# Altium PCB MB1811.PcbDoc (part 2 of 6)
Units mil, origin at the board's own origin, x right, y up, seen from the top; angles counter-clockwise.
Board outline 3480.3 x 4291.34 mil, 4 copper layers (Top Layer, L2_VCC, L3_GND, Bottom Layer), stack 30.59 mil thick; 371 components, 285 nets, 1369 pads, 606 vias.
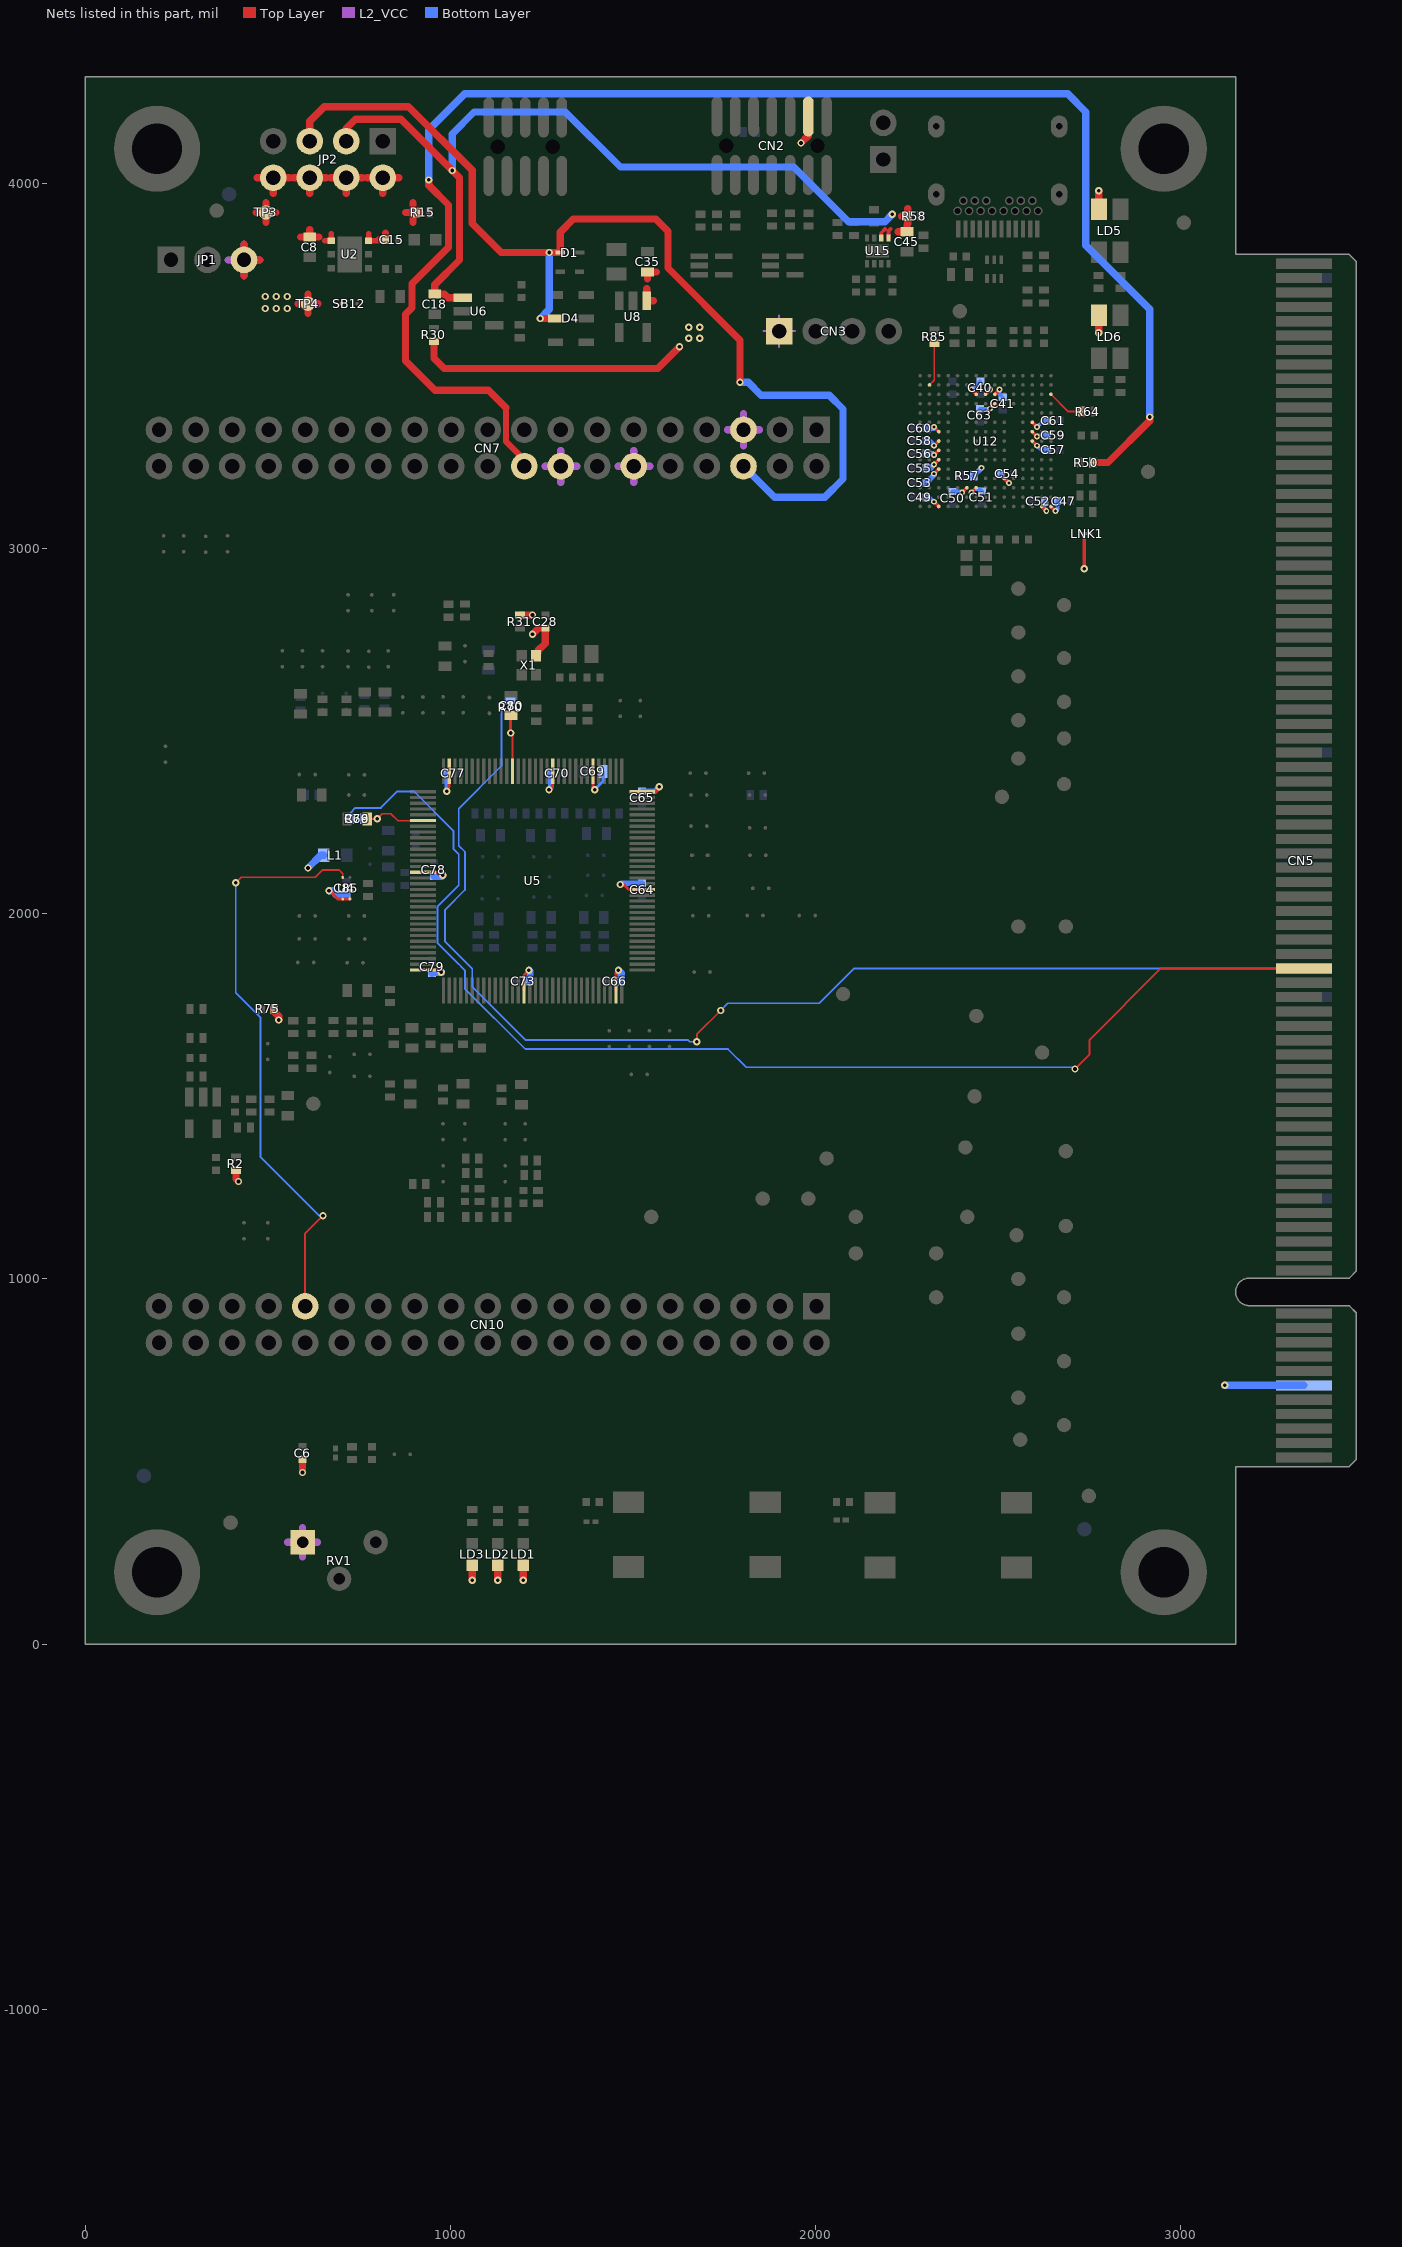
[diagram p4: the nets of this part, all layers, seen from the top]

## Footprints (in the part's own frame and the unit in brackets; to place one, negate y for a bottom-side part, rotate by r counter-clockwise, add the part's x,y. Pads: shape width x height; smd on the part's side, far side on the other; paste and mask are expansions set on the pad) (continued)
ICC_UFBGA201_176+25_10X10_P065 [mm] "IPC"
  round 0.25 smd mask+0.05: A1(-4.55,4.55) A2(-3.9,4.55) A3(-3.25,4.55) A4(-2.6,4.55) A5(-1.95,4.55) A6(-1.3,4.55) A7(-0.65,4.55) A8(0,4.55) A9(0.65,4.55) A10(1.3,4.55) A11(1.95,4.55) A12(2.6,4.55) A13(3.25,4.55) A14(3.9,4.55) A15(4.55,4.55) B1(-4.55,3.9) B2(-3.9,3.9) B3(-3.25,3.9) B4(-2.6,3.9) B5(-1.95,3.9) B6(-1.3,3.9) B7(-0.65,3.9) B8(0,3.9) B9(0.65,3.9) B10(1.3,3.9) B11(1.95,3.9) B12(2.6,3.9) B13(3.25,3.9) B14(3.9,3.9) B15(4.55,3.9) C1(-4.55,3.25) C2(-3.9,3.25) C3(-3.25,3.25) C4(-2.6,3.25) C5(-1.95,3.25) C6(-1.3,3.25) C7(-0.65,3.25) C8(0,3.25) C9(0.65,3.25) C10(1.3,3.25) C11(1.95,3.25) C12(2.6,3.25) C13(3.25,3.25) C14(3.9,3.25) C15(4.55,3.25) D1(-4.55,2.6) D2(-3.9,2.6) D3(-3.25,2.6) D4(-2.6,2.6) D5(-1.95,2.6) D6(-1.3,2.6) D7(-0.65,2.6) D8(0,2.6) D9(0.65,2.6) D10(1.3,2.6) D11(1.95,2.6) D12(2.6,2.6) D13(3.25,2.6) D14(3.9,2.6) D15(4.55,2.6) E1(-4.55,1.95) E2(-3.9,1.95) E3(-3.25,1.95) E4(-2.6,1.95) E12(2.6,1.95) E13(3.25,1.95) E14(3.9,1.95) E15(4.55,1.95) F1(-4.55,1.3) F2(-3.9,1.3) F3(-3.25,1.3) F4(-2.6,1.3) F6(-1.3,1.3) F7(-0.65,1.3) F8(0,1.3) F9(0.65,1.3) F10(1.3,1.3) F12(2.6,1.3) F13(3.25,1.3) F14(3.9,1.3) F15(4.55,1.3) G1(-4.55,0.65) G2(-3.9,0.65) G3(-3.25,0.65) G4(-2.6,0.65) G6(-1.3,0.65) G7(-0.65,0.65) G8(0,0.65) G9(0.65,0.65) G10(1.3,0.65) G12(2.6,0.65) G13(3.25,0.65) G14(3.9,0.65) G15(4.55,0.65) H1(-4.55,0) H2(-3.9,0) H3(-3.25,0) H4(-2.6,0) H6(-1.3,0) H7(-0.65,0) H8(0,0) H9(0.65,0) H10(1.3,0) H12(2.6,0) H13(3.25,0) H14(3.9,0) H15(4.55,0) J1(-4.55,-0.65) J2(-3.9,-0.65) J3(-3.25,-0.65) J4(-2.6,-0.65) J6(-1.3,-0.65) J7(-0.65,-0.65) J8(0,-0.65) J9(0.65,-0.65) J10(1.3,-0.65) J12(2.6,-0.65) J13(3.25,-0.65) J14(3.9,-0.65) J15(4.55,-0.65) K1(-4.55,-1.3) K2(-3.9,-1.3) K3(-3.25,-1.3) K4(-2.6,-1.3) K6(-1.3,-1.3) K7(-0.65,-1.3) K8(0,-1.3) K9(0.65,-1.3) K10(1.3,-1.3) K12(2.6,-1.3) K13(3.25,-1.3) K14(3.9,-1.3) K15(4.55,-1.3) L1(-4.55,-1.95) L2(-3.9,-1.95) L3(-3.25,-1.95) L4(-2.6,-1.95) L12(2.6,-1.95) L13(3.25,-1.95) L14(3.9,-1.95) L15(4.55,-1.95) M1(-4.55,-2.6) M2(-3.9,-2.6) M3(-3.25,-2.6) M4(-2.6,-2.6) M5(-1.95,-2.6) M6(-1.3,-2.6) M7(-0.65,-2.6) M8(0,-2.6) M9(0.65,-2.6) M10(1.3,-2.6) M11(1.95,-2.6) M12(2.6,-2.6) M13(3.25,-2.6) M14(3.9,-2.6) M15(4.55,-2.6) N1(-4.55,-3.25) N2(-3.9,-3.25) N3(-3.25,-3.25) N4(-2.6,-3.25) N5(-1.95,-3.25) N6(-1.3,-3.25) N7(-0.65,-3.25) N8(0,-3.25) N9(0.65,-3.25) N10(1.3,-3.25) N11(1.95,-3.25) N12(2.6,-3.25) N13(3.25,-3.25) N14(3.9,-3.25) N15(4.55,-3.25) P1(-4.55,-3.9) P2(-3.9,-3.9) P3(-3.25,-3.9) P4(-2.6,-3.9) P5(-1.95,-3.9) P6(-1.3,-3.9) P7(-0.65,-3.9) P8(0,-3.9) P9(0.65,-3.9) P10(1.3,-3.9) P11(1.95,-3.9) P12(2.6,-3.9) P13(3.25,-3.9) P14(3.9,-3.9) P15(4.55,-3.9) R1(-4.55,-4.55) R2(-3.9,-4.55) R3(-3.25,-4.55) R4(-2.6,-4.55) R5(-1.95,-4.55) R6(-1.3,-4.55) R7(-0.65,-4.55) R8(0,-4.55) R9(0.65,-4.55) R10(1.3,-4.55) R11(1.95,-4.55) R12(2.6,-4.55) R13(3.25,-4.55) R14(3.9,-4.55) R15(4.55,-4.55)
  silkscreen extent -5.22,-5.07 5.07,5.23, body extent -5.07,-5.07 5.07,5.07, height 0.61
ICC_WSON8-EPAD_2X2_P050 [mm] "MCD-02194"
  rect 0.5x0.3 smd paste+0 mask+0.05: 1(-0.9,0.75) 2(-0.9,0.25) 3(-0.9,-0.25) 4(-0.9,-0.75) 5(0.9,-0.75) 6(0.9,-0.25) 7(0.9,0.25) 8(0.9,0.75)
  rect 0.9x1.6 smd paste+0 mask+0.05: 9(0,0)
  silkscreen extent -0.5,-1 0.5,1, body extent -1,-1 1,1, height 0.81
L0603 [mm]
  rect 0.8x0.95 smd mask+0.05: 1(-0.8,0) 2(0.8,0)
  silkscreen extent -1.33,-0.6 1.33,0.6, body extent -0.87,-0.47 0.87,0.47, height 0.95
LED_0603_OSRAM_LG-Q396-PS-35_GREEN_1A2K_H0P4 [mm]
  rect 0.8x0.8 smd mask+0.05: 1(-0.75,0) 2(0.75,0)
  silkscreen extent -0.85,-0.53 1.28,0.53, body extent -0.85,-0.45 0.85,0.45, height 0.6
LED_0603_OSRAM_LY-Q396-P1Q2-36_YELLOW_1A2K_H0P4 [mm]
  rect 0.8x0.8 smd mask+0.05: 1(-0.75,0) 2(0.75,0)
  silkscreen extent -0.85,-0.53 1.28,0.53, body extent -0.85,-0.45 0.85,0.45, height 0.4
LED_0603_VISHAY_VLMS1300-GS08_RED_1A2K_H0P8 [mm]
  rect 0.8x0.8 smd mask+0.05: 1(-0.75,0) 2(0.75,0)
  silkscreen extent -0.85,-0.53 1.28,0.53, body extent -0.85,-0.45 0.85,0.45, height 0.8
LED_BI-GR_WE-150141SV73110 [mm] "MCD-02631"
  rect 1.1x1.5 smd mask+0.05: 1(-0.75,1.5) 2(0.75,1.5) 3(-0.75,-1.5) 4(0.75,-1.5)
  silkscreen extent -1.65,-1.85 1.5,1.7, body extent -1.5,-1.85 1.5,1.85, height 2.1
LINK200 [mm]
  rect 0.2x0.35 smd paste-10 mask+0.05: 1(0,-0.225) 2(0,0.225)
MOS_SOT23-5L [mm]
  rect 0.6x1.3 smd mask+0.05: 1(-0.95,-1.1) 2(0,-1.1) 3(0.95,-1.1) 4(0.95,1.1) 5(-0.95,1.1)
  silkscreen extent -1.6,-0.95 1.6,0.97, body extent -1.52,-1.25 1.52,1.25, height 1.45
POT_BOURNS_3386P-1-101TLF [mm] "MCD-02026"
  rect 1.7x1.7 hole 0.8 mask+0.05: 1(-2.54,0.02)
  round 1.7 hole 0.8 mask+0.05: 2(0,-2.52) 3(2.54,0.02)
  silkscreen extent -4.8,-4.8 4.8,4.8, body extent -4.8,-4.8 4.8,5.04, height 10.42
PTH_M1261-3005-N_3P5X6_M3_H14 [mm]
  round 6 hole 3.5 mask+0.05: 1(0,0)
  silkscreen extent -3.25,-3.25 3.25,3.25, body extent -2.5,-2.5 2.5,2.5, height 14
R0402 [mm]
  rect 0.51x0.7 smd mask+0.05: 1(-0.45,0) 2(0.45,0)
  body extent -0.52,-0.3 0.52,0.3, height 0.4
SOLDER-BRIDGE_R0603-0R [mil]
  round 10 smd paste-393.7: 1(-19.68,0) 2(23.62,0)
  Top Layer region: -47.24,-19.68 -47.24,19.68 -15.75,19.68 3.94,0 -15.75,-19.68 -47.24,-19.68
  Top Layer region: -5.91,19.68 13.78,0 -5.91,-19.68 47.24,-19.68 47.24,19.68 -5.91,19.68
  silkscreen extent -50,-23 50,23, body extent -36,-20 36,20, height 22
STICKER_BOARD_25X9 [mil] "Sticker to mention board CPN code"
  silkscreen extent -492,-177 492,177
STICKER_PRODUCT_25X9 [mil] "Sticker to mention board CPN code"
  silkscreen extent -492,-177 492,177
SWI_WEALTHMETAL_TD-0341_4P_BLACK [mm]
  rect 1.52x2.16 smd mask+0.05: 1(-2.25,-4.75) 2(-2.25,4.75) 3(2.25,-4.75) 4(2.25,4.75)
  silkscreen extent -3,-3.5 3,3.5, body extent -3,-5.15 3,5.15, height 7.55
SWI_WEALTHMETAL_TD-0341_4P_BLUE [mm]
  rect 1.52x2.16 smd mask+0.05: 1(-2.25,-4.75) 2(-2.25,4.75) 3(2.25,-4.75) 4(2.25,4.75)
  silkscreen extent -3,-3.5 3,3.5, body extent -3,-5.15 3,5.15, height 7.55
TP_SMD_1MM [mm]
  round 1 smd paste-10 mask+0.05: 1(0,0)
  silkscreen extent -0.7,-0.7 0.7,0.7

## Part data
B1: library part MCD-00001, "Push Button, NC, 0.1A, 24V, Black", Manufacturer=WEALTHMETAL, Manufacturer_Part_Number=TD-0341X-A00, Package=6x6mm
B2: library part MCD-00002, "Push Button, NC, 0.1A, 24V, Blue", Manufacturer=WEALTHMETAL, Manufacturer_Part_Number=TD-0341X-GO0, Package=6x6mm
C1 C7 C22 C26: library part MCD-00198, "Capacitor, MLCC, 1nF, 16V, X7R, +/-10%, 0402, T=0.5mm", Manufacturer=YAGEO, Manufacturer_Part_Number=CC0402KRX7R7BB102, Package=0402
C2 C6 C11 C14 C15 C28 C30 C37 C64 C65 C66 C70 C73 C77 C78 C79 C81 C85 C86: library part MCD-00102, "Capacitor, MLCC, 100nF, 16V, X7R, +/-10%, 0402, T=0.5mm", Manufacturer=YAGEO, Manufacturer_Part_Number=CC0402KRX7R7BB104, Package=0402
C3: library part MCD-00012, "Capacitor, MLCC, 2.2uF, 10V, X5R, +/- 10%, 0603, T=0.8mm", Manufacturer=YAGEO, Manufacturer_Part_Number=CC0603KRX5R6BB225, Package=0603
C4 C5 C9 C10 C13 C16 C17 C19 C20 C21 C23 C24 C25 C67 C68 C71 C72 C74 C75 C76 C80: library part MCD-02457, "Capacitor, MLCC, 2.2nF, 50V, C0G/NPO, +/-5%, 0603, T=0,8mm", Manufacturer=YAGEO, Manufacturer_Part_Number=CC0603JRNPO9BN222, Package=0603
C8 C12 C83 C84: library part MCD-00010, "Capacitor, MLCC, 1uF, 16V, X5R, +/-10%, 0603, T=0.8mm", Manufacturer=YAGEO, Manufacturer_Part_Number=CC0603KRX5R7BB105, Package=0603
C18 C35 C45: library part MCD-00099, "Capacitor, MLCC, 10uF, 10V, X5R, +/-10%, 0603, T=0.8mm", Manufacturer=MURATA, Manufacturer_Part_Number=GRM188R61A106KE69D, Package=0603
C27 C46: library part MCD-02355, "Capacitor, MLCC, 100nF, 25V, X7R, +/-10%, 0402, T=0.5mm", Manufacturer=WALSIN, Manufacturer_Part_Number=0402B104K250CT, Package=0402
C29 C31: library part MCD-01374, "Capacitor, MLCC, 5.6pF, 50V, NPO, +/-0.1pF, 0402, T=0.5mm", Manufacturer=YAGEO, Manufacturer_Part_Number=CC0402BRNPO9BN5R6, Package=0402
C32: library part MCD-02372, "Capacitor, MLCC, 2.2uF, 25V, X7R, +/-10%, 0805, T=1,25mm", Manufacturer=MURATA, Manufacturer_Part_Number=GRM21BR71E225KE11L, Package=0805
C33: library part MCD-00016, "Capacitor, MLCC, 20pF, 50V, NPO, +/- 5%, 0402, T=0.5mm", Manufacturer=YAGEO, Manufacturer_Part_Number=CC0402JRNPO9BN200, Package=0402
C34 C36 C87: library part MCD-02198, "Capacitor, MLCC, 10nF, 50V, X7R, +/-10%, 0402, T=0.5mm", Manufacturer=YAGEO, Manufacturer_Part_Number=CC0402KRX7R9BB103, Package=0402
C38 C43 C62: library part MCD-02606, "Capacitor, MLCC, 2.2uF, 6.3V, X5R, +/-10%, 0402, T=0.5mm", Manufacturer=YAGEO, Manufacturer_Part_Number=CC0402KRX5R5BB225, Package=0402
C39 C44: library part MCD-01774, "Capacitor, MLCC, 2.7pF, 50V, NPO, +/-0.1pF, 0402, T=0.5mm", Manufacturer=YAGEO, Manufacturer_Part_Number=CC0402BRNPO9BN2R7, Package=0402
C40 C41 C47 C48 C49 C50 C51 C52 C53 C54 C55 C56 C57 C58 C59 C60 C61 C63: library part MCD-00006, "Capacitor, MLCC, 100nF, 16V, X7R, +/-10%, 0402, T=0.5mm", Manufacturer=YAGEO, Manufacturer_Part_Number=CC0402KRX7R7BB104, Package=0402
C42: library part MCD-00205, "Capacitor, MLCC, 100pF, 50V, NPO, +/-5%, 0402, T=0.5mm", Manufacturer=YAGEO, Manufacturer_Part_Number=CC0402JRNPO9BN101, Package=0402
C69: library part MCD-02196, "Capacitor, MLCC, 4.7uF, 25V, X5R, +/-10%, 0603, T=0.8mm", Manufacturer=TDK, Manufacturer_Part_Number=C1608X5R1E475K080AC, Package=0603
C82: library part MCD-00011, "Capacitor, MLCC, 10nF, 16V, X7R, +/-10%, 0402, T=0.5mm", Manufacturer=YAGEO, Manufacturer_Part_Number=CC0402KRX7R7BB103, Package=0402
CN1: library part MCD-01951, "Header, 5x2, 1.27mm, VR, SMD, T=5.97mm", Manufacturer=SAMTEC, Manufacturer_Part_Number=FTSH-105-01-L-DV-K-A, Package=SMT
CN2: library part MCD-01959, "Header, 7x2, 1.27mm, VR, SMD, T=5.97mm", Manufacturer=SAMTEC, Manufacturer_Part_Number=FTSH-107-01-L-DV-K-A, Package=SMT
CN3: library part MCD-00029, "Header, 4x1, 2.54mm, VR, TH, T=5.84mm/2.54mm", Manufacturer=SAMTEC, Manufacturer_Part_Number=TSW-104-07-G-S
CN4: library part MCD-01108, "USB_TypeC, SMD+DIP, T= 2.96mm (for 1.6mm pcb)", Alternate_Manufacturer=Wurth, Alternate_Manufacturer_Part_Number=632723300011, Manufacturer="CHANT SINCERE (COXOC)", Manufacturer_Part_Number=317JD24BZTF3K3C3
CN5: library part MCD-02436, "PCI EXPRESS x16 Add-in Card Edge-Finger", Manufacturer=N/A
CN7 CN10: library part MCD-00213, "Header, 19x2, 2.54mm, VR, TH, T=5.84mm/10.16mm", Manufacturer=SAMTEC, Manufacturer_Part_Number=TSW-119-09-G-D
D1 D2: library part MCD-01677, "Small signal Schottky diodes", Manufacturer=STMICROELECTRONICS, Manufacturer_HQ_COO=EU, Manufacturer_Part_Number=BAT54KFILM, Package=SOD-523
D3 D4 D5: library part MCD-03011, "Signal Schottky Diode, If=1A, Ifsm=5A, Vf =0.54V@1A, Vrrm=23V, Ir = 0.65µA@5V, SOD-323", Manufacturer=STMICROELECTRONICS, Manufacturer_Part_Number=BAT20JFILM, Package=SOD-323
H1 H2 H3 H4: library part MCD-00035, "POSITION HOLE C6D3R5", Manufacturer=N/A, Manufacturer_Part_Number=n/a
HW1: library part MCD-00235, "Sticker Board 25x9 mm", Manufacturer=N/A
HW2: library part MCD-00547, "Sticker product 25x9 mm", Manufacturer=N/A
JP1: library part MCD-01905, "Header, 3x1, 2.54mm, VR, TH, T=5.84mm/2.54mm", Manufacturer=SAMTEC, Manufacturer_Part_Number=TSW-103-07-G-S
JP2: library part MCD-00686, "Header, 4x2, 2.54mm, VR, TH, T=5.84mm/2.54mm", Manufacturer=SAMTEC, Manufacturer_Part_Number=TSW-104-07-G-D
JP3: library part MCD-00045, "Header, 2x1, 2.54mm, VR, TH, T=5.84mm/2.54mm", Manufacturer=SAMTEC, Manufacturer_Part_Number=TSW-102-07-G-S
L1: library part MCD-00047, "Ferrite bead, 600R @1 00MHz, +/-25%, 350mA, 0R5, 0603, T=0.8mm", Manufacturer=TAI-TECH, Manufacturer_Part_Number=FCM1608KF-601T03, Package=0603
LD1 LD4: library part MCD-00588, "LED Green, 0603 SMD, Forward Voltage Typ=2V, Max=2.5V", Manufacturer="OSRAM OPTO SEMICONDUCTORS", Manufacturer_Part_Number="LG Q396-PS-35", Package="LED 0603"
LD2: library part MCD-00587, "LED Red, 0603 SMD, 2V Forward Voltage", Manufacturer=VISHAY, Manufacturer_Part_Number=VLMS1300-GS08, Package="LED 0603"
LD3: library part MCD-01061, "LED Yellow, 0603 SMD, Forward Voltage min=1.7V, Typ=2V, Max=2.3V", Manufacturer="OSRAM OPTO SEMICONDUCTORS", Manufacturer_Part_Number="LY Q396-P1Q2-36"
LD5 LD6: library part MCD-02631, "LED Bicolor, Green/Red, 2V, 20mA,  4-PLCC", Manufacturer="WURTH ELEKTRONIK", Manufacturer_Part_Number=150141SV73110, Package=4-PLCC
LNK1: library part MCD-02777, "Track link on PCB 200um width for layout routing.", Manufacturer=N/A
R1 R36 R49 R90: library part MCD-00067, "Resistor, 100R, 0402, +/- 1%, 1/16W", Manufacturer=YAGEO, Manufacturer_Part_Number=RC0402FR-07100RL, Package=0402
R2: library part MCD-02456, "Resistor, 4R7, 0402, +/-5%, 1/16W, +/-200ppm/°C", Manufacturer=YAGEO, Manufacturer_Part_Number=RC0402JR-074R7L, Package=0402
R3 R4 R12 R31 R51 R52 R53 R57 R60 R77: library part MCD-00053, "Resistor, 10K, 0402, +/-1%, 1/16W", Manufacturer=YAGEO, Manufacturer_Part_Number=RC0402FR-0710KL, Package=0402
R5 R11 R17 R22 R26 R33 R78 R79 R80 R81 R82 R83: library part MCD-02979, "Resistor, 30K, 0402, +/-0.1%, 1/16W, +/-25ppm/°C", Manufacturer=YAGEO, Manufacturer_Part_Number=RT0402BRD0730KL, Package=0402
R6 R7 R18 R24 R27 R37: library part MCD-02418, "Resistor, 1K, 0402, +/-0.1%, 1/16W, +/-50ppm/°C", Manufacturer=YAGEO, Manufacturer_Part_Number=RT0402BRE071KL, Package=0402
R8 R10 R13 R14 R16 R19 R20 R21 R25 R29 R61 R62 R65 R66 R67 R68 R69 R70 R71 R72 R73: library part MCD-00427, "Resistor, 220R, 0402, +/-1%, 1/16W", Manufacturer=YAGEO, Manufacturer_Part_Number=RC0402FR-07220RL, Package=0402
R9: library part MCD-00481, "Resistor, 47R, 0402, +/-1%, 1/16W", Manufacturer=YAGEO, Manufacturer_Part_Number=RC0402FR-0747RL, Package=0402
R15 R63: library part MCD-00409, "Resistor, 1K8, 0402, +/-1%, 1/16W", Manufacturer=YAGEO, Manufacturer_Part_Number=RC0402FR-071K8L, Package=0402
R23: library part MCD-00178, "Resistor, 470R, 0402, +/-1%, 1/16W", Manufacturer=YAGEO, Manufacturer_Part_Number=RC0402FR-07470RL, Package=0402
R28: library part MCD-00441, "Resistor, 270R, 0402, +/-1%, 1/16W", Manufacturer=YAGEO, Manufacturer_Part_Number=RC0402FR-07270RL, Package=0402
R30 R34 R54 R55 R87: library part MCD-00059, "Resistor, 100K, 0402, +/-1%, 1/16W", Manufacturer=YAGEO, Manufacturer_Part_Number=RC0402FR-07100KL, Package=0402
R32: library part MCD-00461, "Resistor, 360R, 0402, +/-1%, 1/16W", Manufacturer=YAGEO, Manufacturer_Part_Number=RC0402FR-07360RL, Package=0402
R35 R50 R56 R59: library part MCD-00333, "Resistor, 5K1, 0402, +/-1%, 1/16W", Manufacturer=YAGEO, Manufacturer_Part_Number=RC0402FR-075K1L, Package=0402
R38 R39 R41 R42 R43 R64 R74 R75 R76 R91 R92 R93 R94 R95 R96 R97 R98 R99: library part MCD-00052, "Resistor, 0R, 0402, +/-5%, 1/16W", Manufacturer=YAGEO, Manufacturer_Part_Number=RC0402JR-070RL, Package=0402
R40 R44 R45 R85: library part MCD-00455, "Resistor, 33R, 0402, +/-1%, 1/16W", Manufacturer=YAGEO, Manufacturer_Part_Number=RC0402FR-0733RL, Package=0402
R46 R89: library part MCD-00062, "Resistor, 330R, 0402, +/-1%, 1/16W", Manufacturer=YAGEO, Manufacturer_Part_Number=RC0402FR-07330RL, Package=0402
R47 R88: library part MCD-02665, "Resistor, 1K, 0402, +/-0.1%, 1/16W, +/-25ppm/°C", Manufacturer=YAGEO, Manufacturer_Part_Number=RT0402BRD071KL, Package=0402
R48 R58: library part MCD-00185, "Resistor, 3K, 0402, +/-1%, 1/16W", Manufacturer=YAGEO, Manufacturer_Part_Number=RC0402FR-073KL, Package=0402
R84: library part MCD-00381, "Resistor, 1K3, 0402, +/-1%, 1/16W", Manufacturer=YAGEO, Manufacturer_Part_Number=RC0402FR-071K3L, Package=0402
R86: library part MCD-02455, "Resistor, 3K9, 0402, +/-1%, 1/16W, +/-100ppm/°C", Manufacturer=YAGEO, Manufacturer_Part_Number=RC0402FR-073K9L, Package=0402
RV1: library part MCD-02051, "Trimmer, 10K, 3386, +/-10%, 1/2W, T=4.83mm", Manufacturer=BOURNS, Manufacturer_Part_Number=3386P-1-103TLF, Package=3386P
SB1 SB2 SB3 SB4 SB5 SB6 SB7 SB8 SB11 SB12 SB13 SB14 SB15 SB16 SB17 SB18 SB22 SB23 SB26 SB27 SB28 SB29 SB30 SB32 SB33 SB34 SB35 SB36 SB38 SB39 SB40 SB41 SB42 SB43 SB44 SB45 SB46 SB47 SB48 SB50 SB51 SB52 SB53 SB55 SB58 SB59 SB60 SB62 SB65 SB66 SB67 SB68 SB69 SB70 SB71 SB72 SB74 SB75 SB76 SB78 SB79 SB81 SB82 SB83 SB84 SB85 SB86 SB87 SB88 SB89 SB90 SB91 SB92: library part MCD-00071, "Solder Bridge ON", Manufacturer=YAGEO, Manufacturer_Part_Number=RC0603JR-070RL, Package=SB0603
SB9 SB10 SB19 SB20 SB21 SB24 SB25 SB31 SB37 SB49 SB54 SB56 SB57 SB61 SB63 SB64 SB73 SB77 SB80: library part MCD-00072, "Solder Bridge OFF", Manufacturer=YAGEO, Manufacturer_Part_Number=RC0603JR-070RL, Package=SB0603
TP1 TP2 TP3 TP4 TP5 TP6 TP7 TP8 TP9 TP10 TP11 TP12 TP13 TP14 TP15 TP16 TP17 TP18 TP19 TP20 TP21 TP22 TP23 TP24 TP25 TP26 TP27 TP28 TP29 TP30 TP31 TP32 TP33 TP34 TP35 TP36 TP37 TP38 TP39 TP40 TP41 TP42 TP43: library part MCD-00074, "Test Point 1mm", Manufacturer=N/A
U1: library part MCD-01889, "Output rail-to-rail operational amplifiers. Large output swing (+/- 2.4V at VCC  = +/- 2.5V). Operating range: 2.7V to 10V", Manufacturer=STMICROELECTRONICS, Manufacturer_HQ_COO=EU, Package=SOT23-5
U2: library part MCD-00664, "1.2 A low quiescent current LDO with reverse current protection", Manufacturer=STMICROELECTRONICS, Manufacturer_HQ_COO=EU, Package=DFN6
U3 U7 U11: library part MCD-00170, "ESD protection 6V1", Manufacturer=STMICROELECTRONICS, Manufacturer_HQ_COO=EU, Manufacturer_Part_Number=ESDALC6V1-1U2
U4: library part MCD-00668, "Low voltage 0.5 ohm single SPDT switch with break-before-make feature and 15 kV contact ESD protection", Manufacturer=STMICROELECTRONICS, Manufacturer_HQ_COO=EU, Manufacturer_Part_Number=STG4160BJR, Package="Flip Chip 8"
U5: library part MCD-02432, "MCU, Arm Cortex-M4, 32-bit MCU+FPU, up to 512 KB Flash, 128 KB SRAM", Manufacturer=STMICROELECTRONICS, Package=LQFP128
U6: library part MCD-00159, "500mA, Enhanced single channel power switches with active high enable pin", Manufacturer=STMICROELECTRONICS, Manufacturer_HQ_COO=EU
U8: library part MCD-02514, "LDO, 3.3V, 300mA, High input voltage: 2.5V to 28V, SOT23-5L", Manufacturer=STMICROELECTRONICS, Package=SOT23-5L
U9 U10: library part MCD-00136, "Dual Transil array for ESD protection", Manufacturer=STMICROELECTRONICS, Manufacturer_HQ_COO=EU
U12: library part MCD-02706, "MCU, Arm Cortex-M7 32-bit MCU, 512KB Flash, 276KB RAM, With Crypto", Manufacturer=STMICROELECTRONICS, Manufacturer_Part_Number=STM32F723IEK6, Package=BGA176
U13: library part MCD-01207, "High power Transient voltage suppressor:25V/35A EOS and ESD transients protection.", Manufacturer=STMICROELECTRONICS, Manufacturer_HQ_COO=EU, Manufacturer_Part_Number=ESDA25P35-1U1M, Package=QFN1610
U14: library part MCD-00649, "Common mode filter with ESD protection for USB 2.0 interface", Manufacturer=STMICROELECTRONICS, Manufacturer_HQ_COO=EU
U15: library part MCD-02532, "IC, eFuse with Fast Overvoltage Protection 2.7V to 18V 4A 34mOhm 8-Pin WSON", Manufacturer="TEXAS INSTRUMENTS", Package=WSON8
X1: library part MCD-01627, "Oscillator, SPXO, 24MHz, +/-50ppm, square wave, 3V3, 2x1.6mm", Manufacturer=NDK, Manufacturer_Part_Number=NZ2016SH-24MHZ-END4869F, Package=2x1.6mm
X2: library part MCD-01479, "Crystal, 32.768kHz, 6pF, +/-20ppm, 80K, 2.05x1.2mm", Manufacturer=NDK, Manufacturer_Part_Number=NX2012SA-32.768KHZ-EXS00A-MU00527, Package=2.05x1.2mm
X3: library part MCD-01036, "Crystal, 24MHz, 6pF, +/-20ppm, 80R, 2x1.6mm", Manufacturer=NDK, Manufacturer_Part_Number=NX2016SA-24MHZ-EXS00A-CS10820, Package=2x1.6mm

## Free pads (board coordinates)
  round 40 smd far side mask+40: 1(161,461) 1(394,3970) 1(2736,315)
  round 40 smd mask+40: 1(398,333) 1(2748,406) 1(3008,3892)
  round 20 on Mech16: 1(696.46,-1470.16) 1(2619.59,-1470.16)

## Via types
v1: diameter 20, hole 10, Top Layer to Bottom Layer, tented both sides, 524 vias
v2: diameter 16, hole 8, Top Layer to Bottom Layer, tented both sides, 82 vias

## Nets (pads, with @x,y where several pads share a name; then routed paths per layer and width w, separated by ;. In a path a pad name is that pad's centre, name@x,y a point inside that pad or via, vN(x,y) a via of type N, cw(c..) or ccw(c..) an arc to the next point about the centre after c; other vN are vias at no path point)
3V3: C6.2 C28.2 C64.2 C65.2 C66.2 C69.2 C70.2 C73.2 C77.2 C78.2 C79.2 C85.2 CN2.3 CN5.A06 CN7.5 CN7.12 CN7.16 JP1.3 L1.2 LD1.1 LD2.1 LD3.1 LNK1.1 R2.1 R31.2 R75.2 RV1.1 SB12.2 TP4.1 U4.4 U4.5 U5.6 U5.13 U5.31 U5.47 U5.64 U5.79 U5.95 U5.111 U5.128 X1.4 | length 2958.9
  Top Layer w8: v1(667.73,2062.75) 673.97,2056.51 675.4,2056.51 690.71,2041.2 691.55,2040.48 U4.5@724.84,2040.48 ; U5.64@924.99,1845.61 969.41,1845.59 v1(974.99,1840.01) ; U5.47@924.99,2113.32 962.39,2113.31 970.69,2105.01 v1(979.11,2105.01) ; v1(989.99,2335.01) 989.99,2342.21 996.64,2348.86 U5.31@996.64,2389.7 ; U5.79@1201.37,1789.7 1201.37,1831.39 v1(1214.99,1845.01) ; v1(1269.99,2339.69) 1270.31,2340.01 1272.11,2340.01 1280.11,2348.01 U5.13@1280.11,2389.7 ; U5.6@1390.34,2389.7 1390.34,2344.66 1394.99,2340.01 v1(1394.99,2339.65) ; U5.95@1453.34,1789.7 1453.33,1838.35 v1(1459.99,1845.01) ; v1(1464.99,2080.01) 1474.69,2080.01 1480.95,2073.75 1480.95,2073.67 1488.55,2066.06 U5.111@1524.99,2066.08 ; U5.128@1524.99,2333.79 1563.76,2333.78 1572.12,2342.14 v1(1572.12,2347.88)
  Top Layer w10: LNK1.1@2735.01,3040.7 2735.01,2945.22 v1(2735.72,2944.51)
  Top Layer w20: R2.1@412.87,1297.58 412.87,1273.7 v1(419.87,1266.7) ; 434.99,3746.56 JP1.3@434.99,3790 ; 434.99,3833.44 JP1.3@434.99,3790 ; 478.43,3790 JP1.3@434.99,3790 ; R75.2@517.59,1739.7 517.59,1731.98 529.87,1719.7 v1(529.87,1709.06) ; 583.28,3670.01 TP4.1@609.99,3670.01 ; v1(595.27,470.29) C6.2@595.27,505.6 ; 609.99,3643.3 TP4.1@609.99,3670.01 ; 609.99,3696.72 TP4.1@609.99,3670.01 ; 636.7,3670.01 TP4.1@609.99,3670.01 ; v1(1059.83,175.01) LD3.1@1059.83,216.62 ; v1(1129.83,175.01) LD2.1@1129.83,216.62 ; R31.2@1189.99,2817.72 v1(1224.87,2817.72) ; v1(1199.83,175.01) LD1.1@1199.83,216.62 ; v1(1224.99,2765.01) 1242.27,2782.29 C28.2@1259.59,2782.29 ; X1.4@1234.67,2705.59 1239.59,2712.49 1239.59,2719.61 1259.59,2739.61 C28.2@1259.59,2782.29 ; C28.2@1259.99,2782.29 C28.2@1259.59,2782.29 ; v1(1959.99,4110.01) 1979.99,4130.01 CN2.3@1979.99,4182.6
  L2_VCC w20: 391.54,3790.01 JP1.3@434.99,3790 ; 434.98,3746.57 JP1.3@434.99,3790 ; 434.98,3833.45 JP1.3@434.99,3790 ; 478.42,3790.01 JP1.3@434.99,3790 ; 554.77,279.12 RV1.1@595.27,279.11 ; 595.26,238.63 RV1.1@595.27,279.11 ; 595.26,319.61 RV1.1@595.27,279.11 ; 635.75,279.12 RV1.1@595.27,279.11 ; 1258.92,3225.01 CN7.16@1302.37,3225 ; 1302.36,3181.57 CN7.16@1302.37,3225 ; 1302.36,3268.45 CN7.16@1302.37,3225 ; 1345.8,3225.01 CN7.16@1302.37,3225 ; 1458.92,3225.01 CN7.12@1502.37,3225 ; 1502.36,3181.57 CN7.12@1502.37,3225 ; 1502.36,3268.45 CN7.12@1502.37,3225 ; 1545.8,3225.01 CN7.12@1502.37,3225 ; 1758.92,3325.01 CN7.5@1802.37,3325 ; 1802.36,3281.57 CN7.5@1802.37,3325 ; 1802.36,3368.45 CN7.5@1802.37,3325 ; 1845.8,3325.01 CN7.5@1802.37,3325
  Bottom Layer w8: v1(1394.99,2339.65) 1394.99,2340.01 1417.9,2362.92 C69.2@1417.9,2389.69
  Bottom Layer w15: v1(989.99,2335.01) 990.74,2335.76 C77.2@990.74,2384.69 ; v1(1269.99,2339.69) 1269.99,2340.01 1274.2,2344.22 C70.2@1274.2,2384.69 ; v1(1464.99,2080.01) 1468.76,2083.78 C64.2@1524.99,2083.78 ; C65.2@1524.99,2335.75 1559.99,2335.75 v1(1572.12,2347.88)
  Bottom Layer w20: v1(609.99,2125.01) 644.99,2160.01 L1.2@653.49,2160.01 ; v1(667.73,2062.75) 677.25,2062.75 687.71,2052.29 C85.2@714.99,2052.29 ; C79.2@949.99,1837.29 952.71,1840.01 v1(974.99,1840.01) ; C78.2@954.99,2102.3 976.4,2102.3 v1(979.11,2105.01) ; v1(1214.99,1845.01) 1217.7,1842.3 C73.2@1217.71,1815.01 ; v1(1459.99,1845.01) 1467.71,1837.29 C66.2@1467.71,1815.01 ; v1(3119.99,708.67) CN5.A06@3336.8,708.67
  other v1: 492.99,3657.01 522.99,3657.01 552.99,3657.01 492.99,3690.01 522.99,3690.01 552.99,3690.01
3V3_STLK: C35.2 C40.1 C41.1 C47.1 C49.1 C50.1 C51.1 C52.1 C53.1 C54.1 C55.1 C56.1 C57.1 C58.1 C59.1 C60.1 C61.1 C63.1 CN3.1 LD5.4 LD6.4 R30.1 R57.2 U8.1 U12.C1 U12.C5 U12.C6 U12.C7 U12.C8 U12.C9 U12.F3 U12.G3 U12.G13 U12.H13 U12.J12 U12.J13 U12.K4 U12.N8 U12.N9 U12.N10 U12.P1 U12.R1 | length 1972.2
  Top Layer w10: v2(2324.42,3127.78) U12.C1@2337.21,3114.98 ; v2(2324.42,3204.55) U12.C5@2337.22,3217.34 ; v2(2324.43,3230.14) U12.C6@2337.22,3242.93 ; v2(2324.42,3255.73) U12.C7@2337.21,3268.53 ; v2(2324.43,3281.32) U12.C8@2337.22,3294.12 ; v2(2324.42,3332.5) U12.C9@2337.21,3319.71 ; v2(2401.2,3153.37) U12.F3@2413.99,3166.16 ; v2(2426.79,3153.37) U12.G3@2439.58,3166.16 ; v2(2426.78,3434.86) U12.G13@2439.58,3422.07 ; U12.H13@2465.18,3422.07 v2@2477.95,3434.85 ; v2(2476.93,3382.65) U12.J12@2490.77,3396.48 ; U12.J13@2490.77,3422.07 v2(2503.55,3434.87) ; U12.K4@2516.36,3191.75 v2(2529.14,3178.97) ; U12.N8@2593.13,3294.12 v2(2605.92,3281.33) ; U12.N9@2593.13,3319.71 v2(2605.91,3306.92) ; U12.N10@2593.13,3345.3 v2(2605.91,3332.51) ; U12.P1@2618.72,3114.98 v2(2631.51,3102.19) ; U12.R1@2644.31,3114.98 v2(2657.1,3102.19)
  Top Layer w20: R30.1@954.87,3566.98 954.87,3520.8 983.07,3492.6 1567.77,3492.6 v1(1627.07,3551.9) ; 1537.27,3710.62 U8.1@1537.28,3678.01 1556.1,3678.01 ; 1539.87,3737.53 C35.2@1539.87,3757.14 1564.41,3757.15 ; v1(2775.35,3590.18) LD6.4@2775.35,3638.75 ; LD5.4@2775.35,3928.76 v1(2775.35,3979.22)
  L2_VCC w5: 1856.54,3595.01 CN3.1@1899.99,3595 ; 1899.98,3551.57 CN3.1@1899.99,3595 ; 1899.98,3638.45 CN3.1@1899.99,3595 ; 1943.42,3595.01 CN3.1@1899.99,3595
  Bottom Layer w10: C49.1@2302.6,3139.7 2312.5,3139.7 v2(2324.42,3127.78) ; C50.1@2374.7,3155.83 2375.7,3156.83 2397.74,3156.83 v2(2401.2,3153.37) ; v2(2426.79,3153.37) 2435.73,3162.31 2450.18,3162.31 C51.1@2455.18,3157.31 ; v2(2426.78,3434.86) 2444.33,3452.41 2444.87,3452.41 2449.87,3457.41 C40.1@2450.87,3457.41 ; C63.1@2449.87,3382.41 2476.69,3382.41 v2(2476.93,3382.65) ; v2(2503.55,3434.87) 2503.55,3423.03 C41.1@2512.27,3414.31 ; C54.1@2506.99,3204.12 2506.98,3201.13 v2(2529.14,3178.97) ; v2(2605.92,3281.33) 2617.67,3269.58 C57.1@2632.46,3269.58 ; v2(2605.91,3306.92) 2608.57,3309.58 C59.1@2632.46,3309.58 ; v2(2605.91,3332.51) 2622.98,3349.58 C61.1@2632.46,3349.58 ; C52.1@2627.42,3129.12 2627.42,3106.27 v2(2631.51,3102.19)
  Bottom Layer w12: v2(2657.1,3102.19) 2662.16,3107.25 C47.1@2662.16,3129.7
  Bottom Layer w15: C60.1@2302.6,3329.7 2321.62,3329.7 v2(2324.42,3332.5) ; C53.1@2302.91,3179.58 2324.42,3201.09 v2(2324.42,3204.55) ; C55.1@2302.91,3219.58 2313.87,3219.58 v2(2324.43,3230.14) ; C56.1@2302.91,3259.58 2320.57,3259.58 v2(2324.42,3255.73) ; C58.1@2302.91,3294.58 2311.17,3294.58 v2(2324.43,3281.32) ; R57.2@2432.6,3199.7 v2(2453.66,3220.77)
  other v1: 1652.57,3575.6 1682.57,3575.6 1652.57,3605.6 1682.57,3605.6
  other v2: 2477.96,3434.87
5V: C8.2 C15.2 CN7.18 JP2.2 JP2.4 JP2.6 JP2.8 R15.1 R50.2 TP3.1 U2.1 U2.6 | length 5099.7
  Top Layer w15: 656.59,3842.41 U2.1@673.81,3842.41 673.81,3861.19 ; 775.99,3861.01 776.17,3860.83 U2.6@776.18,3842.41 802.62,3842.41
  Top Layer w17: 1152.45,3385.01 1152.45,3292.56 1202.37,3242.64 CN7.18@1202.37,3225
  Top Layer w20: 468.28,3920.01 TP3.1@494.99,3920.01 ; 471.55,4015.01 JP2.8@514.99,4015.01 ; 494.99,3893.3 TP3.1@494.99,3920.01 ; 494.99,3946.72 TP3.1@494.99,3920.01 ; 514.99,3971.57 JP2.8@514.99,4015.01 ; 521.7,3920.01 TP3.1@494.99,3920.01 ; 558.43,4015.01 JP2.8@514.99,4015.01 ; 571.55,4015.01 JP2.6@614.99,4015.01 ; 590.45,3852.57 C8.2@614.99,3852.57 ; 614.99,3872.19 C8.2@614.99,3852.57 ; 614.99,3971.57 JP2.6@614.99,4015.01 ; 639.53,3852.57 C8.2@614.99,3852.57 ; 658.43,4015.01 JP2.6@614.99,4015.01 ; 671.55,4015.01 JP2.4@714.99,4015.01 ; 714.99,3971.57 JP2.4@714.99,4015.01 ; 758.43,4015.01 JP2.4@714.99,4015.01 ; 771.55,4015.01 JP2.2@814.99,4015.01 ; 805.22,3845.01 C15.2@822.28,3845.01 822.28,3863.06 ; 814.99,3971.57 JP2.2@814.99,4015.01 ; 858.43,4015.01 JP2.2@814.99,4015.01 ; 877.81,3920.01 R15.1@897.43,3920.01 ; 897.43,3893.3 R15.1@897.43,3920.01 ; 897.43,3946.72 R15.1@897.43,3920.01 ; R15.1@917.05,3920.01 R15.1@907.27,3920.01 R15.1@897.43,3920.01 ; v1(940.99,4009.01) 940.99,3994.09 994.99,3940.09 994.99,3824.81 894.99,3724.81 894.99,3658.99 877.08,3641.08 877.08,3514 957.78,3433.3 1104.16,3433.3 1152.45,3385.01 ; R50.2@2759.08,3235.3 2800.47,3235.3 2914.87,3349.7 v1(2914.87,3359.7)
  Bottom Layer w20: v1(940.99,4009.01) 940.99,4146.21 1039.48,4244.7 2689.87,4244.7 2739.87,4194.7 2739.87,3829.7 2914.87,3654.7 v1(2914.87,3359.7)
5V_STLK: C18.2 C45.2 JP2.3 R58.1 U6.1 U15.5 U15.6 | length 2469.3
  Top Layer w9: U15.6@2179.72,3850.13 2179.72,3864.55
  Top Layer w10: 2179.72,3864.55 2189.87,3874.7 ; U15.5@2199.41,3850.13 2199.4,3869.23 2204.87,3874.7
  Top Layer w20: JP2.3@714.99,4115.01 714.99,4149.69 740,4174.7 864.87,4174.7 v1(1004.87,4034.7) 1024.99,4014.58 1024.99,3789.82 957.11,3721.94 C18.2@957.11,3696.5 983.51,3696.5 993.67,3686.34 U6.1@1033.81,3686.34 ; 2225.33,3867.26 C45.2@2249.87,3867.26 2249.87,3886.88 ; 2235.1,3909.7 R58.1@2252.16,3909.7 ; 2252.16,3888.9 R58.1@2252.16,3909.7 ; 2252.16,3930.5 R58.1@2252.16,3909.7
  Bottom Layer w20: v1(1004.87,4034.7) 1004.87,4134.7 1064.87,4194.7 1314.87,4194.7 1465.47,4044.1 1940.47,4044.1 2089.87,3894.7 2189.87,3894.7 v1(2209.87,3914.7)
AC_voltage: C80.2 R70.2 U5.20 | length 206.7
  Top Layer w5: C80.2@1164.87,2542.14 1164.87,2494.9 v1(1164.97,2494.8) 1164.97,2494.6 1169.87,2489.7 U5.20@1169.87,2389.7
  Bottom Layer w5: R70.2@1164.87,2546.98 1164.87,2494.9 v1(1164.97,2494.8)
AC_voltage_C: CN5.A33 R70.1 | length 3340.6
  Top Layer w5: v1(1674.87,1649.7) 1674.87,1669.89 v1(1739.99,1735.01)
  Bottom Layer w5: R70.1@1164.87,2582.42 1157.59,2582.42 1139.87,2564.7 1139.87,2404.7 1023.09,2287.92 1023.09,2186.47 1039.99,2169.57 1039.99,2065.02 984.87,2009.9 984.87,1924.69 1060.08,1849.48 1060.08,1799.49 1204.87,1654.7 1649.87,1654.7 1654.87,1649.7 v1(1674.87,1649.7) ; v1(1739.99,1735.01) 1759.68,1754.7 2009.68,1754.7 2105.38,1850.4 CN5.A33@3336.8,1850.4
AC_zero_crossing: C76.2 R69.2 U5.38 | length 204.1
  Top Layer w5: C76.2@772.43,2259.7 v1(799.87,2259.7) 814.03,2273.86 836.97,2273.86 856.54,2254.29 918.76,2254.29 924.24,2254.3 U5.38@924.99,2255.05
  Bottom Layer w5: R69.2@762.59,2259.7 v1(799.87,2259.7)
AC_zero_crossing_C: CN5.B33 R69.1 | length 3386.1
  Top Layer w5: v1(2709.87,1574.7) 2749.87,1614.7 2749.87,1654.89 2945.38,1850.4 CN5.B33@3336.8,1850.4
  Bottom Layer w5: R69.1@727.16,2259.7 727.16,2276.98 739.88,2289.7 809.87,2289.7 854.87,2334.7 900.3,2334.7 1008.09,2226.91 1008.09,2177.7 1022.84,2162.95 1022.84,2077.86 964.87,2019.89 964.87,1919.69 1022.05,1862.51 1022.24,1862.51 1032.49,1852.26 1032.49,1852.07 1039.87,1844.69 1039.87,1794.7 1204.87,1629.7 1759.86,1629.7 1809.86,1579.7 2704.87,1579.7 v1(2709.87,1574.7)
Bridge_USART_RX: R64.1 U12.R13 | length 102.5
  Top Layer w5: U12.R13@2644.31,3422.07 2691.67,3374.7 R64.1@2727.16,3374.7
Bridge_USART_TX: R85.1 U12.B14 | length 119.9
  Top Layer w5: U12.B14@2311.63,3447.66 2324.87,3460.9 2324.87,3468.03 2324.8,3468.1 2324.8,3478.39 2324.87,3478.46 R85.1@2324.87,3561.98
DAC_2_OUT: CN10.29 U4.1 | length 1606.6
  Top Layer w5: v1(412.37,2084.7) 427.68,2100.01 629.99,2100.01 649.99,2120.01 695,2120.01 705.15,2109.86 U4.1@705.15,2099.54 ; CN10.29@602.37,925 602.37,1124.7 v1(651.12,1173.45)
  Bottom Layer w5: v1(412.37,2084.7) 412.37,1783.63 479.99,1716.01 479.99,1334.58 641.12,1173.45 v1(651.12,1173.45)
E5V: CN7.6 D1.1 D4.1 JP2.5 | length 2948.3
  Top Layer w20: JP2.5@614.99,4115.01 614.99,4170.01 654.68,4209.7 885.3,4209.7 1059.87,4035.13 1059.87,3889.69 1139.48,3810.08 v1(1271,3810.08) D1.1@1300.61,3810.08 1300.61,3866.04 1336.47,3901.9 1562.07,3901.9 1595.57,3868.4 1595.57,3767.7 1792.87,3570.4 v1(1792.87,3454.7) ; v1(1245.7,3629.7) D4.1@1287.75,3629.7
  Bottom Layer w20: v1(1245.7,3629.7) 1271,3655 v1(1271,3810.08) ; v1(1792.87,3454.7) 1815.18,3454.7 1850.18,3419.7 2036.98,3419.7 2074.99,3381.69 2074.99,3190.01 2024.99,3140.01 1887.36,3140.01 CN7.6@1802.37,3225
